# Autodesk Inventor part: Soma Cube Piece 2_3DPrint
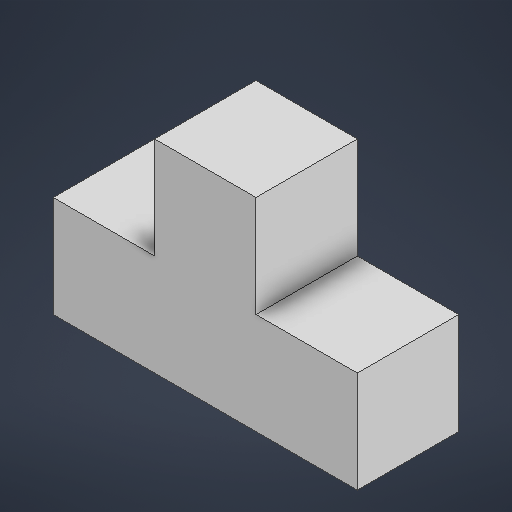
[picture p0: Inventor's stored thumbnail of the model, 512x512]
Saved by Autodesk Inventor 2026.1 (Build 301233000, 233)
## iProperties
Created: 2025-12
Part Number: Soma Cube Piece 2_3DPrint
Material: Generic
Document SubType Name: Modeling
Designer: egberbos000
Density: 1 g/cm^3
Appearance: Default
Author: egberbos000
Part Number: Soma Cube Piece 2
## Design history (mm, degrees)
sketch "Sketch1"
  geometry: L1 (0, 0)-(50.8, 0); L2 (50.8, 0)-(50.8, 25.4); L3 (50.8, 25.4)-(0, 25.4); L4 (0, 25.4)-(0, 0); L5 (50.8, 25.4)-(76.2, 25.4); L6 (76.2, 25.4)-(76.2, 0); L7 (76.2, 0)-(50.8, 0); L8 (50.8, 0)-(50.8, 25.4); L9 (25.4, 25.4)-(50.8, 25.4); L10 (50.8, 25.4)-(50.8, 50.8); L11 (50.8, 50.8)-(25.4, 50.8); L12 (25.4, 50.8)-(25.4, 25.4); 2 further points
  constraints: 24 end point, 6 parallel, 3 horizontal, 3 perpendicular, 1 midpoint
  dimensions: "d0" = 25.4 distance of L1.end L2.end; "d1" = 50.8 distance of L2.end L3.end; "d2" = 25.4 distance of L5.end L6.end (= d0); "d3" = 25.4 distance of L6.end L7.end (= d0); "d4" = 25.4 distance of L10.end L11.end (= d0); "d5" = 25.4 distance of L9.end L10.end (= d0)
extrude "Extrusion1" new body sketch "Sketch1" distance "d6" = 25.4; taper "d7" = 0 deg
body "Solid1"
